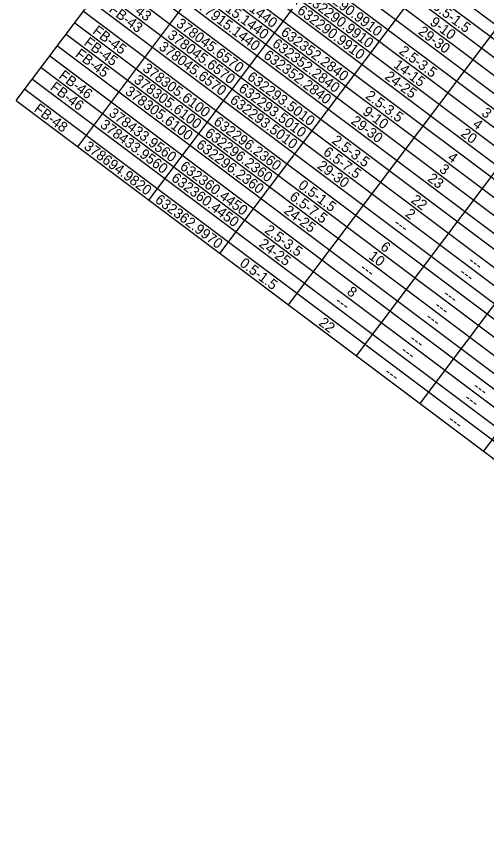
# Model space of a CAD drawing. Extents: x 627484.2 to 627517.5, y 367968.7 to 367996.9.
# Drawn here: x 627489.698 to 627492.236, y 367984.17 to 367988.563 of the extents above; entities that cross this region are included whole.
import ezdxf

# ---------------------------------------------------------------- set-up
doc = ezdxf.new("R2010")
doc.units = 0
doc.layers.add('Default', color=7, linetype='Continuous')

msp = doc.modelspace()

# ---------------------------------------------------------------- linework, layer by layer
at = {"layer": 'Default'}
for p, q in [((627490.4128, 367987.5698), (627493.8348, 367992.127)), ((627490.7966, 367987.2816), (627494.2186, 367991.8387)), ((627489.6976, 367988.1069), (627491.2374, 367990.1574)), ((627490.029, 367987.8581), (627491.5219, 367989.8462)), ((627490.8275, 367989.6116), (627496.0705, 367985.6747)), ((627490.7866, 367989.5571), (627496.0295, 367985.6201)), ((627490.7397, 367989.4947), (627495.9826, 367985.5577)), ((627490.6929, 367989.4323), (627495.9358, 367985.4954)), ((627490.6461, 367989.3699), (627495.889, 367985.433)), ((627490.6051, 367989.3154), (627495.848, 367985.3784)), ((627490.5582, 367989.253), (627495.8011, 367985.316)), ((627490.5114, 367989.1906), (627495.7543, 367985.2537)), ((627490.4646, 367989.1282), (627495.7075, 367985.1913)), ((627490.4236, 367989.0737), (627495.6665, 367985.1367)), ((627490.3767, 367989.0113), (627495.6197, 367985.0743)), ((627491.167, 367987.0035), (627492.6599, 367988.9917)), ((627490.3299, 367988.9489), (627495.5728, 367985.012)), ((627490.2831, 367988.8865), (627495.526, 367984.9496)), ((627490.2421, 367988.832), (627495.485, 367984.895)), ((627490.1953, 367988.7696), (627495.4382, 367984.8326)), ((627490.1484, 367988.7072), (627495.3913, 367984.7703)), ((627491.5334, 367986.7284), (627493.0263, 367988.7165)), ((627490.1016, 367988.6449), (627495.3445, 367984.7079)), ((627490.0606, 367988.5903), (627495.3035, 367984.6533)), ((627490.0138, 367988.5279), (627495.2567, 367984.591)), ((627489.9669, 367988.4655), (627495.2098, 367984.5286)), ((627489.9201, 367988.4032), (627495.163, 367984.4662)), ((627489.8791, 367988.3486), (627495.122, 367984.4116)), ((627489.8323, 367988.2862), (627495.0752, 367984.3493)), ((627489.7854, 367988.2238), (627495.0283, 367984.2869)), ((627489.7445, 367988.1693), (627494.9874, 367984.2323)), ((627489.6976, 367988.1069), (627494.9405, 367984.1699)), ((627491.8765, 367986.4708), (627492.3741, 367987.1335)), ((627492.2195, 367986.2132), (627492.7172, 367986.8759))]:
    msp.add_line(p, q, dxfattribs=at)

# ---------------------------------------------------------------- texts
for s, p in [('377915.1440', (627490.7375, 367988.7548)), ('377915.1440', (627490.6907, 367988.6924)), ('632290.9910', (627491.3028, 367988.7083)), ('FB-43', (627490.2407, 367988.6523)), ('632290.9910', (627491.256, 367988.6459)), ('377915.1440', (627490.6438, 367988.63)), ('0.5-1.5', (627491.9409, 367988.6071)), ('FB-43', (627490.1938, 367988.59)), ('632290.9910', (627491.2091, 367988.5835)), ('378045.6570', (627490.556, 367988.5131)), ('9-10', (627491.9256, 367988.521)), ('FB-45', (627490.1055, 367988.4734)), ('29-30', (627491.8625, 367988.4709)), ('378045.6570', (627490.5092, 367988.4507)), ('632352.2840', (627491.1213, 367988.4666)), ('FB-45', (627490.0586, 367988.4111)), ('378045.6570', (627490.4623, 367988.3883)), ('632352.2840', (627491.0745, 367988.4042)), ('FB-45', (627490.0118, 367988.3487)), ('632352.2840', (627491.0277, 367988.3418)), ('2.5-3.5', (627491.7594, 367988.3654)), ('378305.6100', (627490.3745, 367988.2714)), ('14-15', (627491.7288, 367988.2908)), ('FB-46', (627489.9231, 367988.2324)), ('378305.6100', (627490.3277, 367988.209)), ('632293.5010', (627490.9398, 367988.2249)), ('24-25', (627491.682, 367988.2284)), ('FB-46', (627489.8762, 367988.17)), ('632293.5010', (627490.893, 367988.1625)), ('378305.6100', (627490.2808, 367988.1466)), ('2.5-3.5', (627491.5779, 367988.1237)), ('632293.5010', (627490.8462, 367988.1001)), ('FB-48', (627489.789, 367988.0526)), ('378433.9560', (627490.193, 367988.0297)), ('9-10', (627491.5626, 367988.0377)), ('3', (627492.2042, 367988.0314)), ('29-30', (627491.4995, 367987.9875)), ('378433.9560', (627490.1462, 367987.9673)), ('632296.2360', (627490.7583, 367987.9832)), ('4', (627492.1558, 367987.9702)), ('632296.2360', (627490.7115, 367987.9208)), ('20', (627492.0927, 367987.92)), ('632296.2360', (627490.6647, 367987.8584)), ('2.5-3.5', (627491.3965, 367987.882)), ('378694.9820', (627490.0584, 367987.8504)), ('6.5-7.5', (627491.3496, 367987.8196)), ('4', (627492.0211, 367987.7909)), ('632360.4450', (627490.5769, 367987.7415)), ('29-30', (627491.318, 367987.7458)), ('3', (627491.9759, 367987.7273)), ('632360.4450', (627490.53, 367987.6791)), ('23', (627491.9128, 367987.6772)), ('0.5-1.5', (627491.215, 367987.6403)), ('632362.9970', (627490.4422, 367987.5622)), ('6.5-7.5', (627491.1681, 367987.5779)), ('22', (627491.8236, 367987.5612)), ('24-25', (627491.1375, 367987.5034)), ('2', (627491.793, 367987.4867)), ('---', (627491.7299, 367987.4365)), ('2.5-3.5', (627491.0335, 367987.3986)), ('24-25', (627491.0029, 367987.324)), ('6', (627491.6582, 367987.3074)), ('10', (627491.5951, 367987.2573)), ('0.5-1.5', (627490.8988, 367987.2193)), ('---', (627492.1315, 367987.2325)), ('---', (627491.5484, 367987.1948)), ('---', (627492.0846, 367987.1701)), ('8', (627491.4774, 367987.0653)), ('---', (627491.9968, 367987.0532)), ('---', (627491.4137, 367987.0155)), ('---', (627491.95, 367986.9908)), ('22', (627491.326, 367986.8985)), ('---', (627491.9031, 367986.9284)), ('---', (627491.8153, 367986.8115)), ('---', (627491.7685, 367986.7491)), ('---', (627491.6807, 367986.6322)), ('---', (627492.1584, 367986.5539)), ('---', (627492.1115, 367986.4915)), ('---', (627492.0237, 367986.3746))]:
    msp.add_text(s, height=0.055, rotation=323.0968, dxfattribs=at).set_placement(p)

doc.saveas('drawing.dxf')
